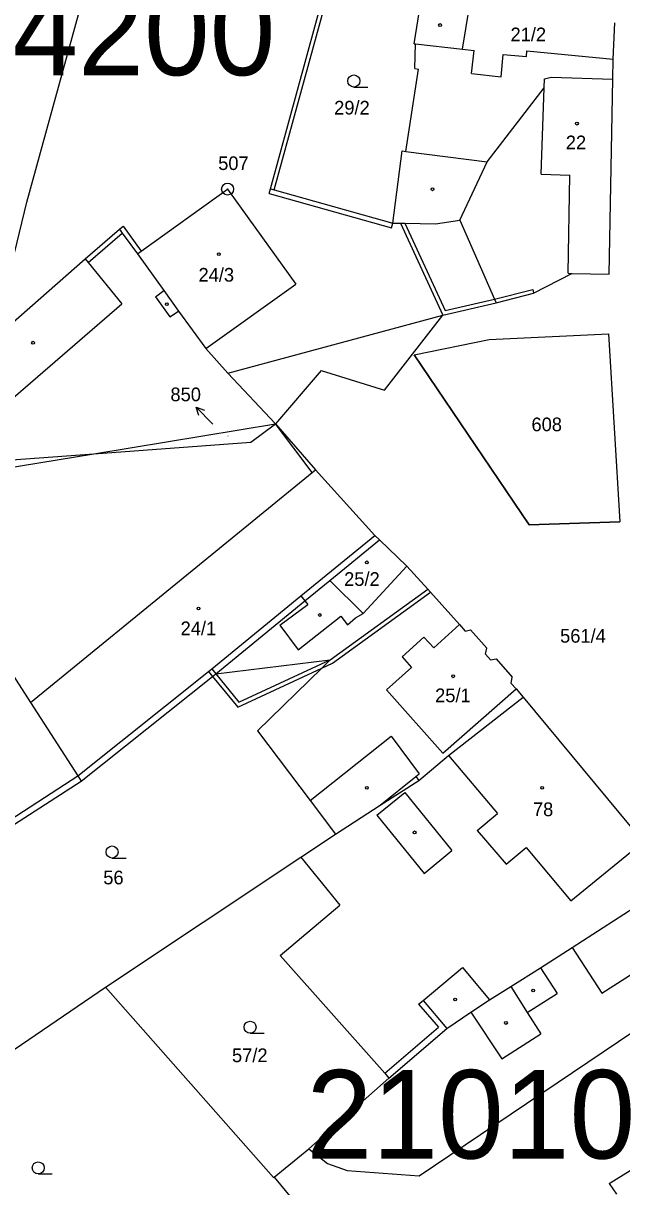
# Model space of a CAD drawing. Extents: x -725765 to -723182, y -1052705 to -1049154.
# Drawn here: x -724894.3 to -724819.8, y -1050916.4 to -1050771.8 of the extents above; entities that cross this region are included whole.
import ezdxf

# ---------------------------------------------------------------- set-up
doc = ezdxf.new("R2010")
doc.units = 0
for name, color, linetype in [('Vrstva 1', 7, 'Continuous'), ('Vrstva 16', 7, 'Continuous'), ('Vrstva 17', 7, 'Continuous'), ('Vrstva 18', 7, 'Continuous'), ('Vrstva 19', 7, 'Continuous'), ('Vrstva 25', 7, 'Continuous'), ('Vrstva 4', 7, 'Continuous'), ('Vrstva 52', 7, 'Continuous'), ('Vrstva 53', 7, 'Continuous')]:
    doc.layers.add(name, color=color, linetype=linetype)

msp = doc.modelspace()

# ---------------------------------------------------------------- linework, layer by layer
at = {"layer": 'Vrstva 1'}
for points in [[(-724863.55, -1050792.32), (-724856.84, -1050767.77)], [(-724845.67, -1050774.3), (-724844.85, -1050769.12)], [(-724839.65, -1050774.99), (-724838.84, -1050769.93)], [(-724820.89, -1050776.23), (-724820.69, -1050771.71)], [(-724845.67, -1050774.3), (-724845.49, -1050774.32)], [(-724845.6, -1050777.39), (-724845.49, -1050774.32)], [(-724845.49, -1050774.32), (-724839.65, -1050774.99)], [(-724846.7, -1050787.68), (-724845.13, -1050777.46)], [(-724845.6, -1050777.39), (-724845.13, -1050777.46)], [(-724820.94, -1050778.69), (-724820.89, -1050776.23)], [(-724829.5, -1050779.79), (-724829.47, -1050778.68)], [(-724829.47, -1050778.68), (-724828.63, -1050778.47)], [(-724828.63, -1050778.47), (-724820.94, -1050778.69)], [(-724821.4, -1050802.96), (-724820.94, -1050778.69)], [(-724836.59, -1050788.99), (-724829.5, -1050779.79)], [(-724848.31, -1050796.6), (-724847.16, -1050787.61)], [(-724847.16, -1050787.61), (-724846.7, -1050787.68)], [(-724839.97, -1050796.22), (-724836.59, -1050788.99)], [(-724879.62, -1050800.08), (-724868.88, -1050792.37)], [(-724868.88, -1050792.37), (-724860.37, -1050804.19)], [(-724863.55, -1050792.32), (-724863.07, -1050792.46)], [(-724863.07, -1050792.46), (-724848.31, -1050796.6)], [(-724843, -1050796.71), (-724839.97, -1050796.22)], [(-724886.61, -1050801.03), (-724882.34, -1050797.36)], [(-724882.34, -1050797.36), (-724881.98, -1050797.85)], [(-724881.98, -1050797.85), (-724880.11, -1050800.42)], [(-724848.31, -1050796.6), (-724847.37, -1050796.59)], [(-724847.37, -1050796.59), (-724846.81, -1050796.61)], [(-724847.37, -1050796.59), (-724842.12, -1050808.04)], [(-724846.81, -1050796.61), (-724843, -1050796.71)], [(-724880.11, -1050800.42), (-724879.62, -1050800.08)], [(-724903.86, -1050816.16), (-724886.61, -1050801.03)], [(-724830.8, -1050805.32), (-724826.03, -1050802.85)], [(-724826.03, -1050802.85), (-724821.4, -1050802.96)], [(-724871.59, -1050812.2), (-724860.37, -1050804.19)], [(-724842.12, -1050808.04), (-724835.48, -1050806.52)], [(-724835.48, -1050806.52), (-724830.8, -1050805.32)], [(-724868.84, -1050815.26), (-724842.12, -1050808.04)], [(-724836.32, -1050811.08), (-724821.47, -1050810.36)], [(-724821.47, -1050810.36), (-724820.09, -1050833.76)], [(-724871.59, -1050812.2), (-724868.84, -1050815.26)], [(-724845.66, -1050812.97), (-724836.32, -1050811.08)], [(-724845.66, -1050812.97), (-724831.35, -1050834.11)], [(-724868.84, -1050815.26), (-724862.9, -1050821.56)], [(-724885.53, -1050825.28), (-724862.9, -1050821.56)], [(-724866.01, -1050823.85), (-724862.9, -1050821.56)], [(-724862.9, -1050821.56), (-724857.93, -1050827.29)], [(-724885.53, -1050825.28), (-724866.01, -1050823.85)], [(-724905.39, -1050826.74), (-724885.53, -1050825.28)], [(-724904.06, -1050828.33), (-724885.53, -1050825.28)], [(-724857.93, -1050827.29), (-724850.58, -1050835.43)], [(-724831.35, -1050834.11), (-724820.09, -1050833.76)], [(-724850.58, -1050835.43), (-724850, -1050835.99)], [(-724856.17, -1050841.04), (-724850, -1050835.99)], [(-724850, -1050835.99), (-724846.6, -1050839.27)], [(-724846.6, -1050839.27), (-724843.97, -1050842.1)], [(-724859.27, -1050843.58), (-724856.17, -1050841.04)], [(-724856.1, -1050850.89), (-724843.97, -1050842.1)], [(-724843.97, -1050842.1), (-724843.64, -1050842.47)], [(-724843.64, -1050842.47), (-724840.04, -1050846.52)], [(-724870.36, -1050852.65), (-724859.27, -1050843.58)], [(-724840.04, -1050846.52), (-724839.33, -1050847.35)], [(-724839.33, -1050847.35), (-724838.65, -1050847.18)], [(-724838.65, -1050847.18), (-724836.63, -1050849.46)], [(-724836.79, -1050850.22), (-724836.63, -1050849.46)], [(-724870.36, -1050852.65), (-724856.1, -1050850.89)], [(-724857.17, -1050851.93), (-724856.1, -1050850.89)], [(-724836.79, -1050850.22), (-724836.18, -1050850.92)], [(-724836.18, -1050850.92), (-724835.46, -1050850.79)], [(-724835.46, -1050850.79), (-724833.46, -1050853.06)], [(-724870.75, -1050852.96), (-724870.36, -1050852.65)], [(-724865.18, -1050859.73), (-724857.17, -1050851.93)], [(-724887.1, -1050865.99), (-724870.75, -1050852.96)], [(-724833.6, -1050853.84), (-724833.46, -1050853.06)], [(-724833.6, -1050853.84), (-724832.99, -1050854.52)], [(-724841.4, -1050862.8), (-724832.11, -1050855.56)], [(-724832.99, -1050854.52), (-724832.11, -1050855.56)], [(-724832.11, -1050855.56), (-724817.19, -1050873.53)], [(-724865.18, -1050859.73), (-724858.59, -1050868.38)], [(-724845.07, -1050865.89), (-724841.4, -1050862.8)], [(-724898.02, -1050872.99), (-724887.1, -1050865.99)], [(-724849.88, -1050868.99), (-724845.07, -1050865.89)], [(-724858.59, -1050868.38), (-724855.44, -1050872.6)], [(-724855.44, -1050872.6), (-724849.88, -1050868.99)], [(-724859.75, -1050875.46), (-724855.44, -1050872.6)], [(-724884.06, -1050891.6), (-724859.75, -1050875.46)], [(-724859.75, -1050875.46), (-724854.9, -1050881.4)], [(-724826.02, -1050886.69), (-724813.15, -1050878.39)], [(-724862.34, -1050887.68), (-724854.9, -1050881.4)], [(-724829.95, -1050889.19), (-724826.02, -1050886.69)], [(-724862.34, -1050887.68), (-724849.32, -1050902.29)], [(-724845.06, -1050915.06), (-724806.9, -1050889.38)], [(-724833.66, -1050891.53), (-724829.95, -1050889.19)], [(-724905.02, -1050905.87), (-724884.06, -1050891.6)], [(-724884.06, -1050891.6), (-724863.15, -1050915.29)], [(-724836.3, -1050893.19), (-724833.66, -1050891.53)], [(-724838.6, -1050894.73), (-724836.3, -1050893.19)], [(-724841.6, -1050896.75), (-724838.6, -1050894.73)], [(-724848.8, -1050902.9), (-724841.6, -1050896.75)], [(-724858.79, -1050911.71), (-724848.8, -1050902.9)], [(-724849.32, -1050902.29), (-724848.8, -1050902.9)], [(-724863.09, -1050915.24), (-724858.79, -1050911.71)], [(-724858.79, -1050911.71), (-724856.46, -1050913.52)], [(-724856.46, -1050913.52), (-724854.02, -1050914.4)], [(-724854.02, -1050914.4), (-724845.06, -1050915.06)], [(-724863.15, -1050915.29), (-724863.09, -1050915.24)], [(-724863.09, -1050915.24), (-724859.58, -1050919.5)]]:
    msp.add_lwpolyline(points, dxfattribs=at)
at = {"layer": 'Vrstva 25'}
for points in [[(-724853.18, -1050779.68), (-724851.43, -1050779.68)], [(-724870.7, -1050821.62), (-724872.8, -1050819.48)], [(-724872.46, -1050820.54), (-724872.8, -1050819.48), (-724871.74, -1050819.84)], [(-724883.26, -1050875.55), (-724881.51, -1050875.55)], [(-724866.08, -1050897.34), (-724864.33, -1050897.34)], [(-724892.44, -1050914.83), (-724890.69, -1050914.83)]]:
    msp.add_lwpolyline(points, dxfattribs=at)
for centre, radius in [((-724842.45, -1050771.97), 0.175), ((-724853.18, -1050778.93), 0.75), ((-724825.41, -1050784.23), 0.175), ((-724868.88, -1050792.37), 0.75), ((-724868.88, -1050792.37), 0.032), ((-724843.38, -1050792.4), 0.175), ((-724869.97, -1050800.47), 0.175), ((-724876.45, -1050806.67), 0.175), ((-724893.09, -1050811.47), 0.175), ((-724851.56, -1050838.79), 0.175), ((-724872.51, -1050844.52), 0.175), ((-724857.41, -1050845.33), 0.175), ((-724840.82, -1050852.95), 0.175), ((-724851.56, -1050866.82), 0.175), ((-724829.73, -1050866.82), 0.175), ((-724845.61, -1050872.36), 0.175), ((-724883.26, -1050874.8), 0.75), ((-724830.86, -1050892.03), 0.175), ((-724840.57, -1050893.13), 0.175), ((-724866.08, -1050896.59), 0.75), ((-724834.25, -1050896.06), 0.175), ((-724892.44, -1050914.08), 0.75)]:
    msp.add_circle(centre, radius, dxfattribs=at)
at = {"layer": 'Vrstva 4'}
for points in [[(-724863.07, -1050792.46), (-724856.34, -1050767.83)], [(-724839.65, -1050774.99), (-724838.22, -1050775.15)], [(-724838.55, -1050777.99), (-724838.22, -1050775.15)], [(-724834.83, -1050778.41), (-724834.59, -1050775.62)], [(-724834.59, -1050775.62), (-724831.7, -1050775.87)], [(-724831.7, -1050775.87), (-724831.64, -1050775.2)], [(-724831.64, -1050775.2), (-724820.89, -1050776.23)], [(-724838.55, -1050777.99), (-724834.83, -1050778.41)], [(-724829.88, -1050790.53), (-724829.5, -1050779.79)], [(-724846.7, -1050787.68), (-724836.59, -1050788.99)], [(-724829.88, -1050790.53), (-724826.28, -1050790.62)], [(-724826.49, -1050802.82), (-724826.28, -1050790.62)], [(-724863.71, -1050792.9), (-724863.55, -1050792.32)], [(-724863.71, -1050792.9), (-724848.47, -1050797.18)], [(-724839.97, -1050796.22), (-724835.68, -1050806.05)], [(-724886.23, -1050801.49), (-724881.98, -1050797.85)], [(-724882.34, -1050797.36), (-724881.88, -1050796.97)], [(-724881.88, -1050796.97), (-724879.62, -1050800.08)], [(-724848.47, -1050797.18), (-724848.31, -1050796.6)], [(-724846.81, -1050796.61), (-724841.83, -1050807.46)], [(-724880.11, -1050800.42), (-724876.8, -1050804.98)], [(-724886.61, -1050801.03), (-724886.23, -1050801.49)], [(-724886.23, -1050801.49), (-724882.02, -1050806.63)], [(-724826.49, -1050802.82), (-724826.03, -1050802.85)], [(-724877.86, -1050805.78), (-724876.8, -1050804.98)], [(-724876.8, -1050804.98), (-724874.98, -1050807.53)], [(-724835.68, -1050806.05), (-724830.92, -1050804.84)], [(-724830.92, -1050804.84), (-724830.8, -1050805.32)], [(-724877.86, -1050805.78), (-724876.08, -1050808.27)], [(-724841.83, -1050807.46), (-724835.68, -1050806.05)], [(-724835.68, -1050806.05), (-724835.48, -1050806.52)], [(-724899.3, -1050821.51), (-724882.02, -1050806.63)], [(-724876.08, -1050808.27), (-724874.98, -1050807.53)], [(-724874.98, -1050807.53), (-724871.59, -1050812.2)], [(-724849.34, -1050817.36), (-724842.12, -1050808.04)], [(-724857.23, -1050814.92), (-724862.9, -1050821.56)], [(-724857.23, -1050814.92), (-724849.34, -1050817.36)], [(-724858.35, -1050827.63), (-724862.9, -1050821.56)], [(-724893.41, -1050856.2), (-724858.35, -1050827.63)], [(-724858.35, -1050827.63), (-724857.93, -1050827.29)], [(-724907.73, -1050834.01), (-724893.41, -1050856.2)], [(-724859.78, -1050842.96), (-724850.58, -1050835.43)], [(-724852, -1050845.15), (-724846.6, -1050839.27)], [(-724856.17, -1050841.04), (-724852, -1050845.15)], [(-724855.83, -1050851.31), (-724843.64, -1050842.47)], [(-724870.86, -1050852.02), (-724859.78, -1050842.96)], [(-724862.37, -1050846.59), (-724858.91, -1050844.02)], [(-724859.78, -1050842.96), (-724859.27, -1050843.58)], [(-724859.27, -1050843.58), (-724858.91, -1050844.02)], [(-724860.11, -1050849.66), (-724854.8, -1050845.48)], [(-724854.8, -1050845.48), (-724853.97, -1050846.54)], [(-724852.98, -1050845.7), (-724852, -1050845.15)], [(-724862.37, -1050846.59), (-724860.11, -1050849.66)], [(-724853.97, -1050846.54), (-724852.98, -1050845.7)], [(-724843.24, -1050849.42), (-724840.04, -1050846.52)], [(-724847.18, -1050850.52), (-724844.47, -1050848.07)], [(-724844.47, -1050848.07), (-724843.24, -1050849.42)], [(-724867.47, -1050856.15), (-724856.1, -1050850.89)], [(-724857.17, -1050851.93), (-724855.83, -1050851.31)], [(-724847.18, -1050850.52), (-724845.99, -1050851.84)], [(-724887.53, -1050865.32), (-724871.26, -1050852.34)], [(-724871.26, -1050852.34), (-724870.86, -1050852.02)], [(-724871.26, -1050852.34), (-724870.75, -1050852.96)], [(-724870.86, -1050852.02), (-724870.36, -1050852.65)], [(-724870.36, -1050852.65), (-724867.47, -1050856.15)], [(-724867.61, -1050856.77), (-724857.17, -1050851.93)], [(-724849.1, -1050854.64), (-724845.99, -1050851.84)], [(-724870.75, -1050852.96), (-724867.61, -1050856.77)], [(-724849.1, -1050854.64), (-724842.12, -1050862.53)], [(-724842.12, -1050862.53), (-724832.99, -1050854.52)], [(-724893.41, -1050856.2), (-724887.53, -1050865.32)], [(-724858.59, -1050868.38), (-724848.51, -1050860.41)], [(-724848.51, -1050860.41), (-724845.05, -1050865.06)], [(-724841.4, -1050862.8), (-724835.31, -1050870.01)], [(-724898.46, -1050872.43), (-724887.53, -1050865.32)], [(-724887.53, -1050865.32), (-724887.1, -1050865.99)], [(-724849.88, -1050868.99), (-724845.47, -1050865.4)], [(-724845.47, -1050865.4), (-724845.05, -1050865.06)], [(-724845.47, -1050865.4), (-724845.07, -1050865.89)], [(-724850.32, -1050870.22), (-724846.84, -1050867.39)], [(-724846.84, -1050867.39), (-724840.97, -1050874.62)], [(-724837.81, -1050872.12), (-724835.31, -1050870.01)], [(-724850.32, -1050870.22), (-724844.44, -1050877.46)], [(-724837.81, -1050872.12), (-724834.22, -1050876.33)], [(-724834.22, -1050876.33), (-724831.73, -1050874.24)], [(-724831.73, -1050874.24), (-724826.16, -1050880.87)], [(-724826.16, -1050880.87), (-724817.19, -1050873.53)], [(-724844.44, -1050877.46), (-724840.97, -1050874.62)], [(-724826.02, -1050886.69), (-724822.3, -1050892.37)], [(-724822.3, -1050892.37), (-724816.8, -1050888.84)], [(-724844.56, -1050893.25), (-724839.67, -1050889.18)], [(-724839.67, -1050889.18), (-724836.3, -1050893.19)], [(-724829.95, -1050889.19), (-724827.88, -1050892.38)], [(-724833.66, -1050891.53), (-724831.59, -1050894.76)], [(-724845.14, -1050893.73), (-724844.56, -1050893.25)], [(-724844.56, -1050893.25), (-724841.6, -1050896.75)], [(-724831.59, -1050894.76), (-724827.88, -1050892.38)], [(-724845.14, -1050893.73), (-724842.63, -1050896.57)], [(-724838.6, -1050894.73), (-724834.74, -1050900.52)], [(-724831.59, -1050894.76), (-724829.91, -1050897.39)], [(-724849.32, -1050902.29), (-724842.63, -1050896.57)], [(-724834.74, -1050900.52), (-724829.91, -1050897.39)], [(-724821.4, -1050916), (-724806.41, -1050906.74)], [(-724821.4, -1050916), (-724820.51, -1050917.36)]]:
    msp.add_lwpolyline(points, dxfattribs=at)
at = {"layer": 'Vrstva 52'}
for points in [[(-724935.31, -1050936), (-724928.81, -1050929), (-724921.81, -1050914), (-724914.81, -1050892), (-724908.69, -1050863), (-724905.5, -1050842), (-724893.88, -1050794), (-724875.69, -1050728), (-724864.81, -1050699), (-724857.19, -1050685), (-724844.38, -1050668), (-724831.88, -1050654), (-724822.88, -1050647), (-724816.5, -1050644), (-724814.99, -1050644), (-724813.33, -1050644)], [(-724821.47, -1050810.36), (-724820.09, -1050833.76), (-724831.35, -1050834.11), (-724845.66, -1050812.97), (-724836.32, -1050811.08), (-724821.47, -1050810.36)]]:
    msp.add_lwpolyline(points, dxfattribs=at)

# ---------------------------------------------------------------- texts
at = {"layer": 'Vrstva 16'}
msp.add_text('850', height=1.7, dxfattribs=at).set_placement((-724875.99, -1050818.75))
at = {"layer": 'Vrstva 17'}
msp.add_text('507', height=1.7, dxfattribs=at).set_placement((-724870.05, -1050790))
at = {"layer": 'Vrstva 18'}
for s, height, p in [('29/2', 1.7, (-724855.62, -1050783.1)), ('608', 1.7, (-724831.07, -1050822.48)), ('850', 0.1, (-724868.92, -1050823.15)), ('561/4', 1.7, (-724827.51, -1050848.77)), ('56', 1.7, (-724884.35, -1050878.82)), ('57/2', 1.7, (-724868.33, -1050900.93))]:
    msp.add_text(s, height=height, dxfattribs=at).set_placement(p)
at = {"layer": 'Vrstva 19'}
for s, p in [('21/2', (-724833.68, -1050773.99)), ('22', (-724826.8, -1050787.42)), ('24/3', (-724872.5, -1050803.88)), ('25/2', (-724854.38, -1050841.71)), ('24/1', (-724874.73, -1050847.84)), ('25/1', (-724843.06, -1050856.17)), ('78', (-724830.89, -1050870.34))]:
    msp.add_text(s, height=1.7, dxfattribs=at).set_placement(p)
at = {"layer": 'Vrstva 53'}
for s, p in [('24200', (-724903.83, -1050778.21)), ('21010', (-724859.06, -1050912.91))]:
    msp.add_text(s, height=11, dxfattribs=at).set_placement(p)

doc.saveas('drawing.dxf')
